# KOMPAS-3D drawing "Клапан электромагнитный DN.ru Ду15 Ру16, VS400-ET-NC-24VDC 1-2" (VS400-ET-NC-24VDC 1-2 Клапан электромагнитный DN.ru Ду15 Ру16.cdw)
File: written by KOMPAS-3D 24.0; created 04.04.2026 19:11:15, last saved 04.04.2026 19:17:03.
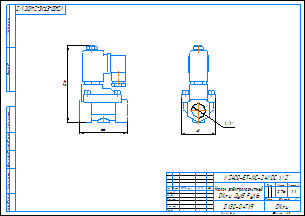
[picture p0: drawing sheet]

Document properties: c3d_UniqueCompID: ef56311e-7521-43dc-8291-0e6108b3d81d; Обозначение: VS400-ET-NC-220VAC 1-2; Наименование: Клапан электромагнитный DN.ru Ду15 Ру16; Автор: artio; Класс точности: c; Знак неуказанной шероховатости: Шероховатость не задана; Рассекать на разрезах: Да; c3d_UniqueCompID: ef56311e-7521-43dc-8291-0e6108b3d81d; Обозначение: VS400-ET-NC-220VAC 3-8; Наименование: Клапан электромагнитный DN.ru Ду10 Ру16; Автор: artio; Класс точности: c; Знак неуказанной шероховатости: Шероховатость не задана; Рассекать на разрезах: Да; Автор: artio; Форматы листов документа: A3; Полное имя файла: VS400-ET-NC-24VDC 1-2 Клапан электромагнитный DN.ru Ду15 Ру16.m3d; Масса: 0.759; Наименование: Клапан электромагнитный DN.ru Ду15 Ру16; Количество листов документа: 1; Примечание: D130-04719

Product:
- Body: Тело 1  | qty 1
    Масса: 1.030062
- Part/product: Клапан электромагнитный DN.ru Ду15 Ру16  | designation VS400-ET-NC-24VDC 1-2
    Масса: 0.759
    Раздел спецификации: Прочие изделия
    Примечание: D130-04719
    additional columns: ef56311e-7521-43dc-8291-0e6108b3d81d; VS400-ET-NC-220VAC 1-2; artio; c; Шероховатость не задана; Да

Views: Вид 1, Спереди, Проекционный вид 2
Referenced files in C:\Users\artio\OneDrive\Рабочий стол\Клапан электромагнитный DN.ru\VS400-ET-NC\VS400-ET-NC-24VDC\: VS400-ET-NC-24VDC 3-8 Клапан электромагнитный DN.ru Ду10 Ру16.m3d, VS400-ET-NC-24VDC 1-2 Клапан электромагнитный DN.ru Ду15 Ру16.m3d
Referenced files in C:\Users\artio\OneDrive\Рабочий стол\Клапан электромагнитный DN.ru\VS400-ET-NC\: VS400-ET-NC-24VDC 3-8 Клапан электромагнитный DN.ru Ду10 Ру16.cdw
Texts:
  VS400-ET-NC-24VDC 1-2
  Клапан электромагнитный
  DN.ru Ду15 Ру16
  VS400-ET-NC-24VDC 1/2"
  VS400-ET-NC-24VDC 1/2"-
  Клапан электромагнитный DN.ru Ду15 Ру16
  VS400-ET-NC-24VDC 1-2 Клапан электромагнитный DN.ru Ду15 Ру16
Dimensions and other numbers on the sheet: 0; 3; 2; 4; 48; 1/2"; 66; 106; 1:1; 1; 0,76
